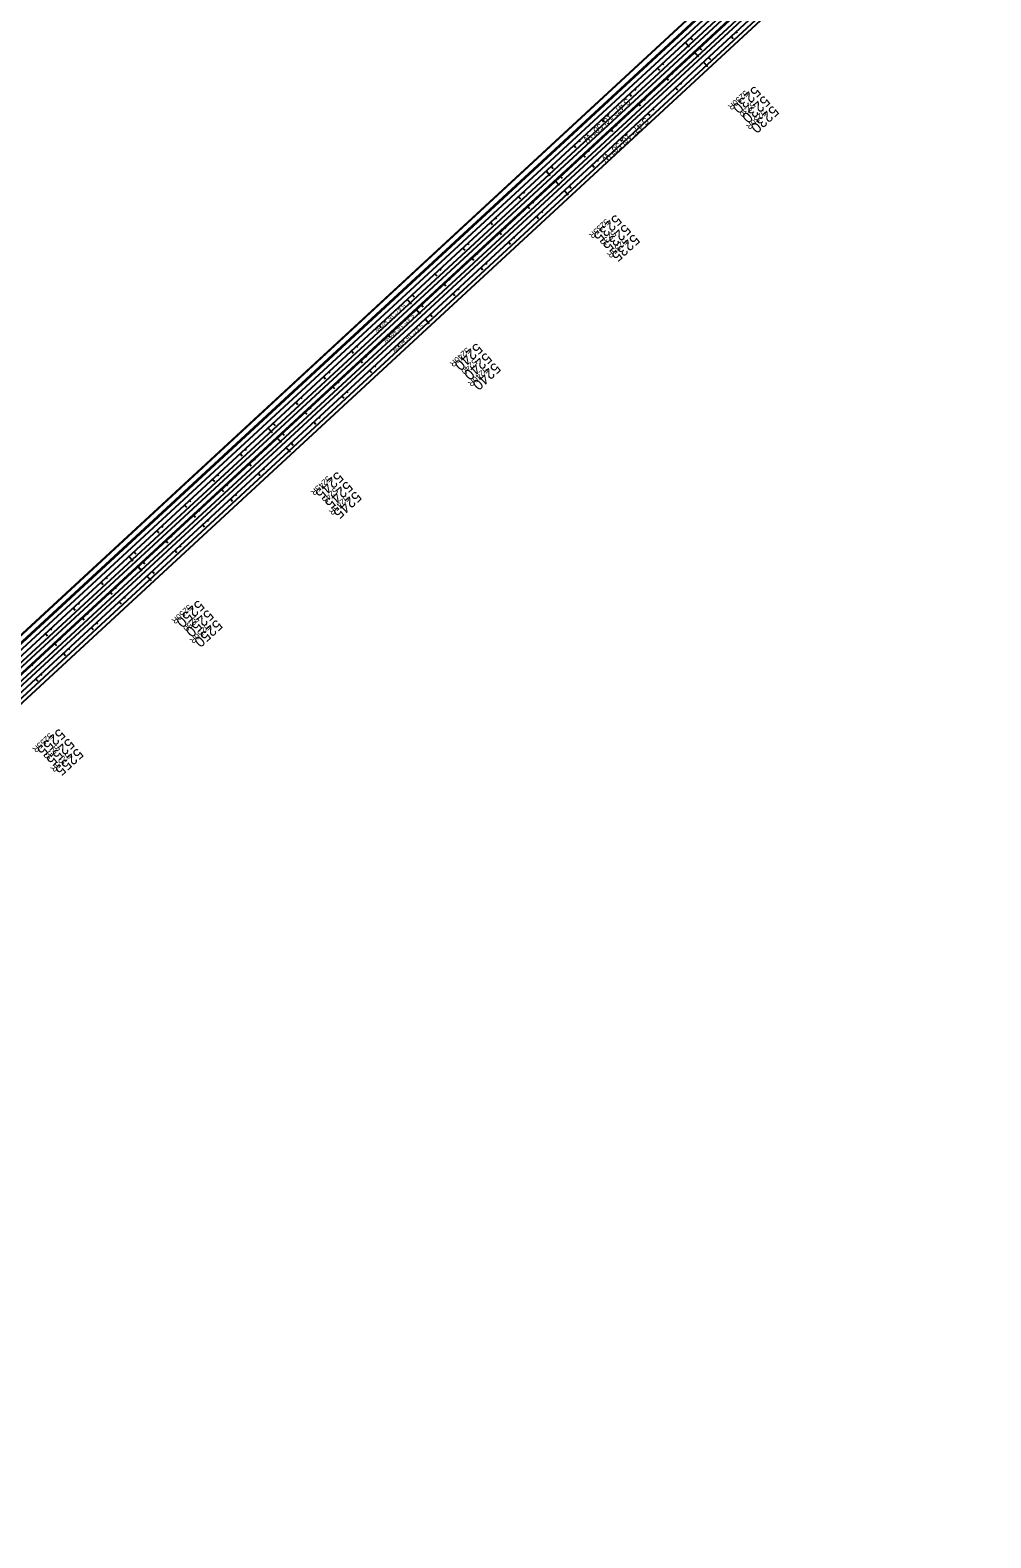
# Model space of a CAD drawing. Extents: x 2160876 to 2175990, y 601436 to 618246.
# Drawn here: x 2166193 to 2168731, y 605855 to 609834 of the extents above; entities that cross this region are included whole.
import ezdxf

# ---------------------------------------------------------------- set-up
doc = ezdxf.new("R2010")
doc.units = 0
for name, color, linetype in [('BNDY-ADJ', 7, 'Continuous'), ('BNDY-ADJ-TXT', 7, 'Continuous'), ('EX-UTIL-ELEC-TXT', 7, 'Continuous'), ('GN_Transparent 80', 7, 'Continuous'), ('RD_DTM_Major2', 7, 'Continuous'), ('RD_EX_BldgApp_Steps', 7, 'Continuous'), ('RD_EX_DV_TX_Prop', 7, 'Continuous'), ('RD_EX_Parking_Conc', 7, 'Continuous'), ('RD_HC_Cl', 7, 'Continuous'), ('RD_HC_Data_Tic', 7, 'Continuous'), ('RD_HC_TX_Sta50', 7, 'Continuous'), ('RD_TX_RoadID', 7, 'Continuous')]:
    doc.layers.add(name, color=color, linetype=linetype)

msp = doc.modelspace()

# ---------------------------------------------------------------- linework, layer by layer
at = {"layer": 'BNDY-ADJ'}
msp.add_line((2172239.9, 613739.9), (2163704.8, 605858.6), dxfattribs=at)
at = {"layer": 'BNDY-ADJ-TXT'}
for p, q in [((2168658.1, 610480.3), (2165572.4, 607631)), ((2168705.8, 610428.6), (2165620.1, 607579.3))]:
    msp.add_line(p, q, dxfattribs=at)
at = {"layer": 'EX-UTIL-ELEC-TXT'}
for p, q in [((2168630.1, 610510.7), (2165544.4, 607661.4)), ((2168630.7, 610509.9), (2165545.1, 607660.6)), ((2168650, 610489.1), (2165564.3, 607639.8)), ((2168658.1, 610480.3), (2165572.4, 607631)), ((2168666.2, 610471.5), (2165580.6, 607622.2)), ((2168697.7, 610437.5), (2165612, 607588.1)), ((2168705.8, 610428.6), (2165620.1, 607579.3)), ((2168714, 610419.8), (2165628.3, 607570.5))]:
    msp.add_line(p, q, dxfattribs=at)
at = {"layer": 'GN_Transparent 80'}
for p, q in [((2168640.2, 610499.7), (2165554.6, 607650.3)), ((2168641.8, 610497.9), (2165556.1, 607648.6)), ((2168454, 610245.6), (2165100.2, 607148.7)), ((2168455.6, 610243.9), (2165101.8, 607146.9))]:
    msp.add_line(p, q, dxfattribs=at)
at = {"layer": 'RD_DTM_Major2'}
for p, q in [((2167947.3, 609776.1), (2167958.1, 609764.3)), ((2167873.8, 609708.2), (2167879.2, 609702.3)), ((2167800.3, 609640.4), (2167805.8, 609634.5)), ((2167726.9, 609572.5), (2167732.3, 609566.7)), ((2167653.4, 609504.7), (2167658.8, 609498.8)), ((2167579.9, 609436.9), (2167590.8, 609425.1)), ((2167506.5, 609369), (2167511.9, 609363.1)), ((2167433, 609301.2), (2167438.4, 609295.3)), ((2167359.5, 609233.3), (2167365, 609227.5)), ((2167286.1, 609165.5), (2167291.5, 609159.6)), ((2167212.6, 609097.7), (2167223.4, 609085.9)), ((2167139.1, 609029.8), (2167144.6, 609023.9)), ((2167065.7, 608962), (2167071.1, 608956.1)), ((2166992.2, 608894.1), (2166997.6, 608888.3)), ((2166918.7, 608826.3), (2166924.1, 608820.4)), ((2166845.2, 608758.5), (2166856.1, 608746.7)), ((2166771.8, 608690.6), (2166777.2, 608684.7)), ((2166698.3, 608622.8), (2166703.7, 608616.9)), ((2166624.8, 608554.9), (2166630.3, 608549.1)), ((2166551.4, 608487.1), (2166556.8, 608481.2)), ((2166477.9, 608419.2), (2166488.8, 608407.5)), ((2166404.4, 608351.4), (2166409.9, 608345.5)), ((2166331, 608283.6), (2166336.4, 608277.7)), ((2166257.5, 608215.7), (2166262.9, 608209.8))]:
    msp.add_line(p, q, dxfattribs=at)
at = {"layer": 'RD_EX_BldgApp_Steps'}
for p, q in [((2172672.7, 614139.6), (2163700.6, 605854.7)), ((2169773.5, 611510.3), (2165657.1, 607709.2)), ((2169821.3, 611458.6), (2165682.4, 607636.8)), ((2168058, 609830.5), (2168060.7, 609827.5)), ((2167936.8, 609814.3), (2167942.3, 609808.4)), ((2167960.7, 609788.5), (2167966.1, 609782.6)), ((2167984.5, 609762.6), (2167990, 609756.7)), ((2167863.4, 609746.4), (2167866.1, 609743.5)), ((2167887.2, 609720.6), (2167889.9, 609717.7)), ((2167789.9, 609678.6), (2167792.6, 609675.7)), ((2167911.1, 609694.8), (2167913.8, 609691.8)), ((2167813.8, 609652.8), (2167816.5, 609649.8)), ((2167716.4, 609610.8), (2167719.1, 609607.8)), ((2167837.6, 609626.9), (2167840.3, 609624)), ((2167740.3, 609584.9), (2167743, 609582)), ((2167764.1, 609559.1), (2167766.9, 609556.2)), ((2167643, 609542.9), (2167645.7, 609540)), ((2167666.8, 609517.1), (2167669.5, 609514.1)), ((2167569.5, 609475.1), (2167574.9, 609469.2)), ((2167690.7, 609491.3), (2167693.4, 609488.3)), ((2167593.3, 609449.2), (2167598.8, 609443.4)), ((2167496, 609407.2), (2167498.7, 609404.3)), ((2167617.2, 609423.4), (2167622.6, 609417.5)), ((2167519.9, 609381.4), (2167522.6, 609378.5)), ((2167543.7, 609355.6), (2167546.4, 609352.6)), ((2167422.6, 609339.4), (2167425.3, 609336.5)), ((2167446.4, 609313.6), (2167449.1, 609310.6)), ((2167349.1, 609271.6), (2167351.8, 609268.6)), ((2167470.3, 609287.7), (2167473, 609284.8)), ((2167372.9, 609245.7), (2167375.7, 609242.8)), ((2167275.6, 609203.7), (2167278.3, 609200.8)), ((2167396.8, 609219.9), (2167399.5, 609216.9)), ((2167299.5, 609177.9), (2167302.2, 609174.9)), ((2167323.3, 609152), (2167326, 609149.1)), ((2167202.1, 609135.9), (2167207.6, 609130)), ((2167226, 609110), (2167231.4, 609104.2)), ((2167249.9, 609084.2), (2167255.3, 609078.3)), ((2167128.7, 609068), (2167131.4, 609065.1)), ((2167152.5, 609042.2), (2167155.2, 609039.3)), ((2167055.2, 609000.2), (2167057.9, 608997.3)), ((2167176.4, 609016.4), (2167179.1, 609013.4)), ((2167079.1, 608974.4), (2167081.8, 608971.4)), ((2166981.7, 608932.4), (2166984.5, 608929.4)), ((2167102.9, 608948.5), (2167105.6, 608945.6)), ((2167005.6, 608906.5), (2167008.3, 608903.6)), ((2167029.5, 608880.7), (2167032.2, 608877.7)), ((2166908.3, 608864.5), (2166911, 608861.6)), ((2166932.1, 608838.7), (2166934.8, 608835.7)), ((2166834.8, 608796.7), (2166840.2, 608790.8)), ((2166956, 608812.8), (2166958.7, 608809.9)), ((2166858.7, 608770.8), (2166864.1, 608765)), ((2166761.3, 608728.8), (2166764, 608725.9)), ((2166882.5, 608745), (2166887.9, 608739.1)), ((2166785.2, 608703), (2166787.9, 608700.1)), ((2166809.1, 608677.2), (2166811.8, 608674.2)), ((2166687.9, 608661), (2166690.6, 608658.1)), ((2166711.7, 608635.2), (2166714.4, 608632.2)), ((2166614.4, 608593.2), (2166617.1, 608590.2)), ((2166735.6, 608609.3), (2166738.3, 608606.4)), ((2166638.3, 608567.3), (2166641, 608564.4)), ((2166540.9, 608525.3), (2166543.6, 608522.4)), ((2166662.1, 608541.5), (2166664.8, 608538.5)), ((2166564.8, 608499.5), (2166567.5, 608496.5)), ((2166588.6, 608473.6), (2166591.4, 608470.7)), ((2166467.5, 608457.5), (2166472.9, 608451.6)), ((2166491.3, 608431.6), (2166496.7, 608425.8)), ((2166515.2, 608405.8), (2166520.6, 608399.9)), ((2166394, 608389.6), (2166396.7, 608386.7)), ((2166417.9, 608363.8), (2166420.6, 608360.9)), ((2166320.5, 608321.8), (2166323.2, 608318.8)), ((2166441.7, 608338), (2166444.4, 608335)), ((2166344.4, 608296), (2166347.1, 608293)), ((2166247.1, 608253.9), (2166249.8, 608251)), ((2166368.2, 608270.1), (2166371, 608267.2)), ((2166270.9, 608228.1), (2166273.6, 608225.2)), ((2166294.8, 608202.3), (2166297.5, 608199.3)), ((2166197.4, 608160.3), (2166200.2, 608157.3)), ((2166221.3, 608134.4), (2166224, 608131.5))]:
    msp.add_line(p, q, dxfattribs=at)
at = {"layer": 'RD_HC_Cl'}
for p, q in [((2167923.5, 609801.9), (2167934.3, 609790.2)), ((2168044.6, 609818.1), (2168050.1, 609812.2)), ((2167971.2, 609750.3), (2167982, 609738.5)), ((2167850, 609734.1), (2167855.4, 609728.2)), ((2167897.7, 609682.4), (2167903.1, 609676.5)), ((2167776.5, 609666.3), (2167781.9, 609660.4)), ((2167703, 609598.4), (2167708.5, 609592.5)), ((2167824.2, 609614.6), (2167829.7, 609608.7)), ((2167629.6, 609530.6), (2167635, 609524.7)), ((2167750.8, 609546.7), (2167756.2, 609540.9)), ((2167677.3, 609478.9), (2167682.7, 609473)), ((2167556.1, 609462.7), (2167567, 609451)), ((2167482.6, 609394.9), (2167488.1, 609389)), ((2167603.8, 609411.1), (2167614.7, 609399.3)), ((2167409.2, 609327), (2167414.6, 609321.2)), ((2167530.4, 609343.2), (2167535.8, 609337.3)), ((2167456.9, 609275.4), (2167462.3, 609269.5)), ((2167335.7, 609259.2), (2167341.1, 609253.3)), ((2167262.2, 609191.4), (2167267.7, 609185.5)), ((2167383.4, 609207.5), (2167388.8, 609201.7)), ((2167188.8, 609123.5), (2167199.6, 609111.8)), ((2167310, 609139.7), (2167315.4, 609133.8)), ((2167236.5, 609071.9), (2167247.3, 609060.1)), ((2167115.3, 609055.7), (2167120.7, 609049.8)), ((2167163, 609004), (2167168.4, 608998.1)), ((2167041.8, 608987.8), (2167047.3, 608982)), ((2166968.4, 608920), (2166973.8, 608914.1)), ((2167089.5, 608936.2), (2167095, 608930.3)), ((2166894.9, 608852.2), (2166900.3, 608846.3)), ((2167016.1, 608868.3), (2167021.5, 608862.5)), ((2166942.6, 608800.5), (2166948, 608794.6)), ((2166821.4, 608784.3), (2166832.3, 608772.6)), ((2166748, 608716.5), (2166753.4, 608710.6)), ((2166869.1, 608732.6), (2166880, 608720.9)), ((2166674.5, 608648.6), (2166679.9, 608642.8)), ((2166795.7, 608664.8), (2166801.1, 608658.9)), ((2166722.2, 608597), (2166727.6, 608591.1)), ((2166601, 608580.8), (2166606.4, 608574.9)), ((2166527.6, 608513), (2166533, 608507.1)), ((2166648.7, 608529.1), (2166654.2, 608523.2)), ((2166454.1, 608445.1), (2166464.9, 608433.4)), ((2166575.3, 608461.3), (2166580.7, 608455.4)), ((2166380.6, 608377.3), (2166386, 608371.4)), ((2166501.8, 608393.4), (2166512.7, 608381.7)), ((2166428.3, 608325.6), (2166433.8, 608319.7)), ((2166307.1, 608309.4), (2166312.6, 608303.6)), ((2166233.7, 608241.6), (2166239.1, 608235.7)), ((2166354.9, 608257.8), (2166360.3, 608251.9)), ((2166281.4, 608189.9), (2166286.8, 608184)), ((2166207.9, 608122.1), (2166213.4, 608116.2))]:
    msp.add_line(p, q, dxfattribs=at)
at = {"layer": 'RD_TX_RoadID'}
for p, q in [((2168641.8, 610497.9), (2165556.1, 607648.6)), ((2168673, 610464.1), (2165587.4, 607614.8)), ((2168690.9, 610444.8), (2165605.2, 607595.5)), ((2168720.7, 610412.5), (2165635.1, 607563.2))]:
    msp.add_line(p, q, dxfattribs=at)

# ---------------------------------------------------------------- texts
at = {"layer": 'RD_EX_BldgApp_Steps'}
for s, height, p in [('5230', 28, (2168107.3, 609688.6)), ('S 47° 16\' 50" W', 17, (2167769.4, 609655.9)), ('5230', 28, (2168131.8, 609663.4)), ('5230', 28, (2168155, 609636.9)), ('S 47° 16\' 50" W', 17, (2167818.1, 609604.8)), ('5235', 28, (2167739.9, 609349.3)), ('5235', 28, (2167764.4, 609324.1)), ('5235', 28, (2167787.6, 609297.7)), ('5240', 28, (2167372.6, 609010.2)), ('5240', 28, (2167397.1, 608984.9)), ('5240', 28, (2167420.3, 608958.5)), ('5245', 28, (2167005.2, 608670.9)), ('5245', 28, (2167029.7, 608645.7)), ('5245', 28, (2167052.9, 608619.2)), ('5250', 28, (2166637.9, 608331.8)), ('5250', 28, (2166662.4, 608306.5)), ('5250', 28, (2166685.6, 608280.1)), ('5255', 28, (2166270.5, 607992.5)), ('5255', 28, (2166295, 607967.2)), ('5255', 28, (2166318.2, 607940.8))]:
    msp.add_text(s, height=height, rotation=222.7195, dxfattribs=at).set_placement(p)
at = {"layer": 'RD_EX_DV_TX_Prop'}
for s, p in [('5230', (2168100.1, 609646.2)), ('5235', (2167732.4, 609306.6)), ('5240', (2167365.4, 608967.7)), ('5245', (2166997.7, 608628.2)), ('5250', (2166630.8, 608289.3)), ('5255', (2166263.1, 607949.8))]:
    msp.add_text(s, height=16, rotation=222.7195, dxfattribs=at).set_placement(p)
at = {"layer": 'RD_EX_Parking_Conc'}
msp.add_text('S 47° 16\' 50" W', height=10.8, rotation=222.7195, dxfattribs=at).set_placement((2167202.1, 609087.8))
at = {"layer": 'RD_HC_Data_Tic'}
for s, p in [('5230R', (2168081.1, 609676.5)), ('5230R', (2168128.8, 609624.8)), ('5235R', (2167713.8, 609337.3)), ('5235R', (2167761.5, 609285.6)), ('5240R', (2167346.4, 608998.1)), ('5240R', (2167394.2, 608946.4)), ('5245R', (2166979.1, 608658.9)), ('5245R', (2167026.8, 608607.2)), ('5250R', (2166611.8, 608319.7)), ('5250R', (2166659.5, 608268)), ('5255R', (2166244.4, 607980.5)), ('5255R', (2166292.1, 607928.8))]:
    msp.add_text(s, height=16, rotation=222.7195, dxfattribs=at).set_placement(p)
at = {"layer": 'RD_HC_TX_Sta50'}
for p in [(2167179.3, 609113.6), (2167226.3, 609061.4)]:
    msp.add_text('S 47° 16\' 50" W', height=10.8, rotation=222.7195, dxfattribs=at).set_placement(p)

doc.saveas('drawing.dxf')
